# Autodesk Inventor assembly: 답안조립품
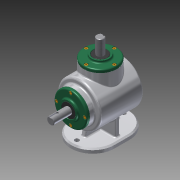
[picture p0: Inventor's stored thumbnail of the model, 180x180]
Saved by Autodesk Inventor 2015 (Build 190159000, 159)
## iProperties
Created: 2016-04
Part Number: 답안조립품
Document SubType Name: Assembly
Designer: Administrator
Author: Administrator
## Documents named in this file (14)
- C:\Users\Administrator\Desktop\460407V1012\답안조립품.iam
- C:\Users\Administrator\Desktop\460407V1012\본체.ipt
- C:\Users\Administrator\Desktop\460407V1012\커버.ipt
- C:\Users\Administrator\Desktop\460407V1012\베어링 6203.ipt
- C:\Users\Administrator\Desktop\460407V1012\메인 축.ipt
- 메인 축.ipt
- C:\Users\Administrator\Desktop\460407V1012\오일실 17 32 8.ipt
- C:\Users\Administrator\Desktop\460407V1012\키 5x5.ipt
- C:\Users\Administrator\Desktop\460407V1012\메인 베벨기어.ipt
- C:\Users\Administrator\Desktop\460407V1012\서브 축.ipt
- 서브 축.ipt
- C:\Users\Administrator\Desktop\460407V1012\키 4x4.ipt
- C:\Users\Administrator\Desktop\460407V1012\서브 베벨기어.ipt
- C:\Users\Administrator\Desktop\460407V1012\M4.ipt
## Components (8 placed, 1 different names)
1. M4:1 — 각도:5
2. M4:3
3. M4:4
4. M4:5
5. M4:2 — 각도:4
6. M4:6
7. M4:7
8. M4:8
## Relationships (2: Angle 2)
- 각도:4 [Angle]: M4:2
- 각도:5 [Angle]: M4:1
